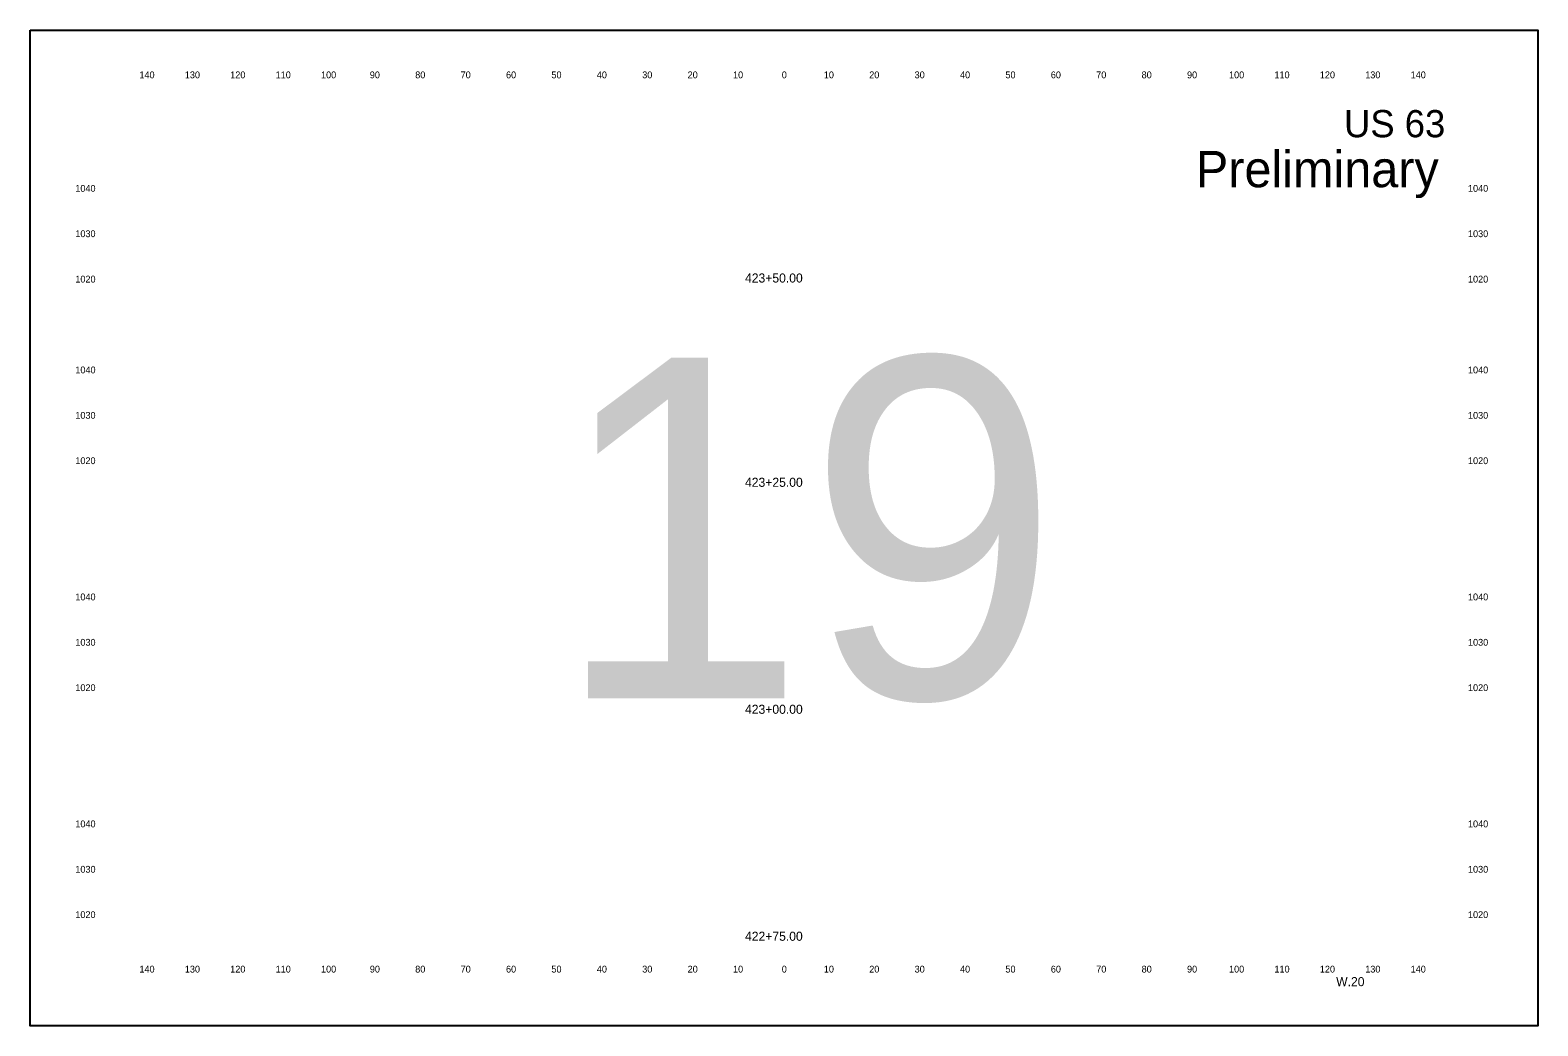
# Model space of a CAD drawing. Extents: x 10123 to 17295, y 9730 to 10181.
# Drawn here: x 16603.2 to 16935.3, y 9730.3 to 9949.6 of the extents above; entities that cross this region are included whole.
import ezdxf

# ---------------------------------------------------------------- set-up
doc = ezdxf.new("R2010")
doc.units = 0
for name, color, linetype in [('dsnTextCpn', 7, 'Continuous'), ('dsnTextCpnTitleSheetLocDesc', 7, 'Continuous'), ('dsnTextCpnTitleSheetPIN', 7, 'Continuous'), ('dsnTextCpnTitleSheetWorkType', 7, 'Continuous')]:
    doc.layers.add(name, color=color, linetype=linetype)

msp = doc.modelspace()

# ---------------------------------------------------------------- linework, layer by layer
at = {"layer": 'dsnTextCpnTitleSheetWorkType'}
msp.add_lwpolyline([(16603.21, 9949.6), (16935.29, 9949.6), (16935.29, 9730.26), (16603.21, 9730.26)], close=True, dxfattribs=at)

# ---------------------------------------------------------------- texts
at = {"layer": 'dsnTextCpn'}
for s, height, p in [('140', 1.5, (16627.27, 9939)), ('130', 1.5, (16637.27, 9939)), ('120', 1.5, (16647.27, 9939)), ('110', 1.5, (16657.27, 9939)), ('100', 1.5, (16667.27, 9939)), ('90', 1.5, (16678.02, 9939)), ('80', 1.5, (16688.02, 9939)), ('70', 1.5, (16698.02, 9939)), ('60', 1.5, (16708.02, 9939)), ('50', 1.5, (16718.02, 9939)), ('40', 1.5, (16728.02, 9939)), ('30', 1.5, (16738.02, 9939)), ('20', 1.5, (16748.02, 9939)), ('10', 1.5, (16758.02, 9939)), ('0', 1.5, (16768.76, 9939)), ('0', 1.5, (16768.76, 9939)), ('10', 1.5, (16778.02, 9939)), ('20', 1.5, (16788.02, 9939)), ('30', 1.5, (16798.02, 9939)), ('40', 1.5, (16808.02, 9939)), ('50', 1.5, (16818.02, 9939)), ('60', 1.5, (16828.02, 9939)), ('70', 1.5, (16838.02, 9939)), ('80', 1.5, (16848.02, 9939)), ('90', 1.5, (16858.02, 9939)), ('100', 1.5, (16867.27, 9939)), ('110', 1.5, (16877.27, 9939)), ('120', 1.5, (16887.27, 9939)), ('130', 1.5, (16897.27, 9939)), ('140', 1.5, (16907.27, 9939)), ('US 63', 6, (16892.6, 9926)), ('1040', 1.5, (16613.15, 9914)), ('1040', 1.5, (16919.9, 9914)), ('1030', 1.5, (16613.15, 9904)), ('1030', 1.5, (16919.9, 9904)), ('1020', 1.5, (16613.15, 9894)), ('423+50.00', 2, (16760.66, 9894)), ('1020', 1.5, (16919.9, 9894)), ('1040', 1.5, (16613.15, 9874)), ('1040', 1.5, (16919.9, 9874)), ('1030', 1.5, (16613.15, 9864)), ('1030', 1.5, (16919.9, 9864)), ('1020', 1.5, (16613.15, 9854)), ('1020', 1.5, (16919.9, 9854)), ('423+25.00', 2, (16760.66, 9849)), ('1040', 1.5, (16613.15, 9824)), ('1040', 1.5, (16919.9, 9824)), ('1030', 1.5, (16613.15, 9814)), ('1030', 1.5, (16919.9, 9814)), ('1020', 1.5, (16613.15, 9804)), ('1020', 1.5, (16919.9, 9804)), ('423+00.00', 2, (16760.66, 9799)), ('1040', 1.5, (16613.15, 9774)), ('1040', 1.5, (16919.9, 9774)), ('1030', 1.5, (16613.15, 9764)), ('1030', 1.5, (16919.9, 9764)), ('1020', 1.5, (16613.15, 9754)), ('1020', 1.5, (16919.9, 9754)), ('422+75.00', 2, (16760.66, 9749)), ('140', 1.5, (16627.27, 9742)), ('130', 1.5, (16637.27, 9742)), ('120', 1.5, (16647.27, 9742)), ('110', 1.5, (16657.27, 9742)), ('100', 1.5, (16667.27, 9742)), ('90', 1.5, (16678.02, 9742)), ('80', 1.5, (16688.02, 9742)), ('70', 1.5, (16698.02, 9742)), ('60', 1.5, (16708.02, 9742)), ('50', 1.5, (16718.02, 9742)), ('40', 1.5, (16728.02, 9742)), ('30', 1.5, (16738.02, 9742)), ('20', 1.5, (16748.02, 9742)), ('10', 1.5, (16758.02, 9742)), ('0', 1.5, (16768.76, 9742)), ('0', 1.5, (16768.76, 9742)), ('10', 1.5, (16778.02, 9742)), ('20', 1.5, (16788.02, 9742)), ('30', 1.5, (16798.02, 9742)), ('40', 1.5, (16808.02, 9742)), ('50', 1.5, (16818.02, 9742)), ('60', 1.5, (16828.02, 9742)), ('70', 1.5, (16838.02, 9742)), ('80', 1.5, (16848.02, 9742)), ('90', 1.5, (16858.02, 9742)), ('100', 1.5, (16867.27, 9742)), ('110', 1.5, (16877.27, 9742)), ('120', 1.5, (16887.27, 9742)), ('130', 1.5, (16897.27, 9742)), ('140', 1.5, (16907.27, 9742))]:
    msp.add_text(s, height=height, dxfattribs=at).set_placement(p)
at = {"layer": 'dsnTextCpnTitleSheetLocDesc'}
msp.add_text('Preliminary', height=8, dxfattribs=at).set_placement((16859.97, 9915))
at = {"layer": 'dsnTextCpnTitleSheetPIN'}
msp.add_text('W.20', height=2, dxfattribs=at).set_placement((16890.87, 9739))
at = {"layer": 'dsnTextCpnTitleSheetWorkType'}
msp.add_text('19', height=75, dxfattribs=at).set_placement((16718.46, 9802.43))

doc.saveas('drawing.dxf')
